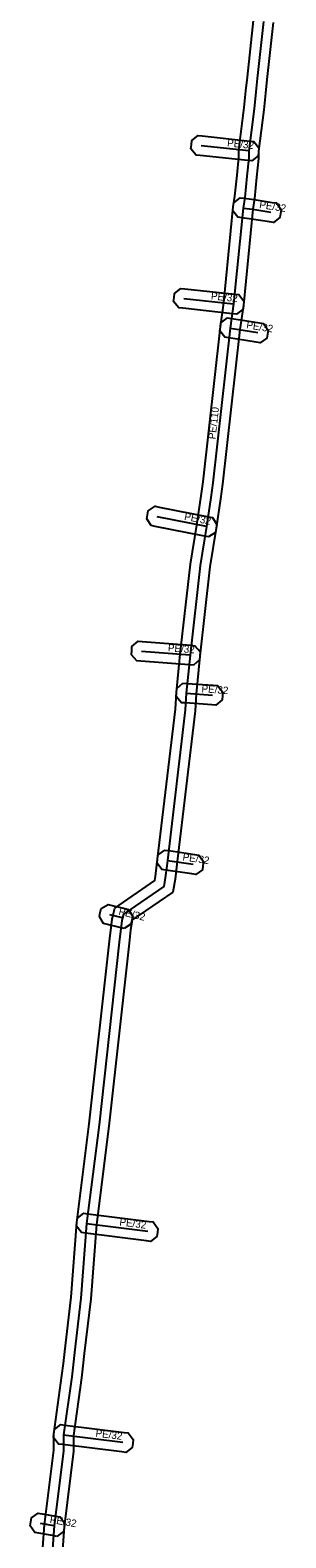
# Model space of a CAD drawing. Extents: x -772893 to -772575, y -1033735 to -1033288.
# Drawn here: x -772764.4 to -772738.4, y -1033585.9 to -1033432.5 of the extents above; entities that cross this region are included whole.
import ezdxf

# ---------------------------------------------------------------- set-up
doc = ezdxf.new("R2010")
doc.units = 0
for name, color, linetype in [('1', 7, 'Continuous'), ('24', 7, 'Continuous'), ('30', 7, 'Continuous')]:
    doc.layers.add(name, color=color, linetype=linetype)

msp = doc.modelspace()

# ---------------------------------------------------------------- linework, layer by layer
at = {"layer": '1'}
for points in [[(-772763.07, -1033586.93), (-772762.91, -1033584.62), (-772761.96, -1033577.01), (-772761.96, -1033575.38), (-772761.13, -1033569.41), (-772760.99, -1033568.21), (-772760.85, -1033566.96), (-772760.2, -1033561.44), (-772759.61, -1033553.84), (-772758.35, -1033543.8), (-772756.3, -1033525.22), (-772756.14, -1033523.82), (-772756.02, -1033523), (-772755.97, -1033522.67), (-772755.77, -1033521.86), (-772751.69, -1033519.06), (-772751.61, -1033518.63), (-772751.47, -1033517.44), (-772751.41, -1033516.89), (-772749.58, -1033501.62), (-772749.49, -1033499.91), (-772749.1, -1033496.02), (-772748.07, -1033486.85), (-772747.42, -1033482.88), (-772746.98, -1033479.92), (-772746.78, -1033478.48), (-772745.02, -1033462.72), (-772744.66, -1033460.27), (-772743.71, -1033450.5), (-772743.54, -1033449.42), (-772743.33, -1033447.28), (-772743.14, -1033445.47), (-772743.14, -1033444.74), (-772742.6, -1033440.4), (-772742.42, -1033438.71), (-772742.27, -1033437.33), (-772741.64, -1033431.55)], [(-772739.65, -1033431.75), (-772740.28, -1033437.55), (-772740.43, -1033438.93), (-772740.61, -1033440.63), (-772741.14, -1033444.86), (-772741.14, -1033445.58), (-772741.34, -1033447.48), (-772741.55, -1033449.67), (-772741.73, -1033450.76), (-772742.68, -1033460.51), (-772743.04, -1033462.98), (-772744.79, -1033478.73), (-772745, -1033480.21), (-772745.44, -1033483.19), (-772746.09, -1033487.12), (-772747.11, -1033496.22), (-772747.49, -1033500.07), (-772747.59, -1033501.79), (-772749.42, -1033517.12), (-772749.49, -1033517.68), (-772749.63, -1033518.93), (-772749.87, -1033520.24), (-772754.01, -1033523.07), (-772754.04, -1033523.29), (-772754.15, -1033524.08), (-772754.31, -1033525.44), (-772756.37, -1033544.03), (-772757.62, -1033554.04), (-772758.2, -1033561.63), (-772758.86, -1033567.19), (-772759, -1033568.44), (-772759.15, -1033569.66), (-772759.96, -1033575.52), (-772759.96, -1033577.13), (-772760.91, -1033584.82), (-772761.08, -1033587.14)]]:
    msp.add_lwpolyline(points, dxfattribs=at)
for points in [[(-772741.83, -1033445.84), (-772742.24, -1033445.79), (-772747.08, -1033445.28), (-772747.49, -1033445.24), (-772748.01, -1033444.6), (-772747.96, -1033444.19), (-772747.92, -1033443.77), (-772747.28, -1033443.25), (-772746.86, -1033443.3), (-772742.04, -1033443.81), (-772741.62, -1033443.85), (-772741.1, -1033444.49), (-772741.15, -1033444.91), (-772741.19, -1033445.32)], [(-772743, -1033449.59), (-772742.59, -1033449.64), (-772741.58, -1033449.77), (-772739.74, -1033450.05), (-772739.33, -1033450.11), (-772738.84, -1033450.78), (-772738.9, -1033451.19), (-772738.96, -1033451.6), (-772739.63, -1033452.09), (-772740.04, -1033452.03), (-772741.86, -1033451.75), (-772742.85, -1033451.62), (-772743.26, -1033451.57), (-772743.77, -1033450.91), (-772743.71, -1033450.5), (-772743.66, -1033450.09)], [(-772749.04, -1033458.8), (-772748.63, -1033458.85), (-772743.56, -1033459.4), (-772743.15, -1033459.44), (-772742.63, -1033460.09), (-772742.68, -1033460.5), (-772742.72, -1033460.91), (-772743.37, -1033461.43), (-772743.78, -1033461.38), (-772748.85, -1033460.83), (-772749.26, -1033460.79), (-772749.78, -1033460.14), (-772749.73, -1033459.73), (-772749.69, -1033459.32)], [(-772744.3, -1033461.8), (-772743.89, -1033461.86), (-772742.99, -1033461.99), (-772741.05, -1033462.3), (-772740.64, -1033462.37), (-772740.16, -1033463.04), (-772740.22, -1033463.45), (-772740.29, -1033463.86), (-772740.96, -1033464.34), (-772741.37, -1033464.28), (-772743.29, -1033463.97), (-772744.18, -1033463.84), (-772744.58, -1033463.78), (-772745.08, -1033463.11), (-772745.02, -1033462.71), (-772744.96, -1033462.3)], [(-772746.22, -1033484.09), (-772746.62, -1033484.01), (-772751.64, -1033483.02), (-772752.05, -1033482.94), (-772752.51, -1033482.25), (-772752.43, -1033481.85), (-772752.35, -1033481.44), (-772751.66, -1033480.98), (-772751.26, -1033481.06), (-772746.24, -1033482.05), (-772745.83, -1033482.13), (-772745.37, -1033482.82), (-772745.45, -1033483.22), (-772745.53, -1033483.63)], [(-772747.77, -1033497.15), (-772748.19, -1033497.12), (-772753.12, -1033496.74), (-772753.53, -1033496.71), (-772754.07, -1033496.08), (-772754.04, -1033495.66), (-772754.01, -1033495.25), (-772753.38, -1033494.71), (-772752.96, -1033494.74), (-772748.03, -1033495.12), (-772747.62, -1033495.16), (-772747.08, -1033495.78), (-772747.11, -1033496.2), (-772747.15, -1033496.61)], [(-772748.83, -1033498.96), (-772748.42, -1033498.99), (-772745.74, -1033499.19), (-772745.33, -1033499.22), (-772744.79, -1033499.85), (-772744.82, -1033500.27), (-772744.85, -1033500.68), (-772745.48, -1033501.22), (-772745.9, -1033501.19), (-772748.57, -1033500.99), (-772748.98, -1033500.96), (-772749.52, -1033500.33), (-772749.49, -1033499.92), (-772749.46, -1033499.5)], [(-772750.68, -1033515.95), (-772750.27, -1033516.01), (-772747.63, -1033516.4), (-772747.22, -1033516.46), (-772746.73, -1033517.12), (-772746.79, -1033517.54), (-772746.85, -1033517.95), (-772747.51, -1033518.44), (-772747.92, -1033518.38), (-772750.56, -1033517.99), (-772750.97, -1033517.93), (-772751.46, -1033517.27), (-772751.4, -1033516.86), (-772751.34, -1033516.45)], [(-772754.82, -1033523.93), (-772755.23, -1033523.83), (-772756.5, -1033523.52), (-772756.9, -1033523.42), (-772757.33, -1033522.71), (-772757.23, -1033522.31), (-772757.13, -1033521.91), (-772756.42, -1033521.48), (-772756.02, -1033521.58), (-772754.75, -1033521.89), (-772754.35, -1033521.99), (-772753.92, -1033522.7), (-772754.02, -1033523.1), (-772754.12, -1033523.5)], [(-772758.91, -1033552.9), (-772758.49, -1033552.95), (-772752.28, -1033553.74), (-772751.87, -1033553.79), (-772751.37, -1033554.45), (-772751.42, -1033554.86), (-772751.47, -1033555.27), (-772752.12, -1033555.77), (-772752.54, -1033555.72), (-772758.75, -1033554.93), (-772759.16, -1033554.88), (-772759.66, -1033554.22), (-772759.61, -1033553.81), (-772759.56, -1033553.4)], [(-772761.25, -1033574.41), (-772760.84, -1033574.46), (-772754.81, -1033575.21), (-772754.4, -1033575.26), (-772753.89, -1033575.91), (-772753.94, -1033576.32), (-772753.99, -1033576.73), (-772754.64, -1033577.24), (-772755.05, -1033577.19), (-772761.08, -1033576.44), (-772761.49, -1033576.39), (-772762, -1033575.74), (-772761.95, -1033575.33), (-772761.9, -1033574.92)], [(-772761.67, -1033585.78), (-772762.08, -1033585.71), (-772763.48, -1033585.47), (-772763.89, -1033585.4), (-772764.37, -1033584.72), (-772764.3, -1033584.31), (-772764.23, -1033583.9), (-772763.55, -1033583.42), (-772763.14, -1033583.49), (-772761.74, -1033583.73), (-772761.33, -1033583.8), (-772760.85, -1033584.48), (-772760.92, -1033584.89), (-772760.99, -1033585.3)]]:
    msp.add_lwpolyline(points, close=True, dxfattribs=at)
at = {"layer": '24'}
for points in [[(-772740.65, -1033431.65), (-772741.28, -1033437.44), (-772741.43, -1033438.82), (-772741.6, -1033440.52), (-772742.14, -1033444.8), (-772742.14, -1033445.53), (-772742.33, -1033447.38), (-772742.55, -1033449.55), (-772742.72, -1033450.63), (-772743.67, -1033460.39), (-772744.03, -1033462.85), (-772745.79, -1033478.6), (-772745.99, -1033480.07), (-772746.43, -1033483.03), (-772747.08, -1033486.99), (-772748.11, -1033496.12), (-772748.49, -1033499.99), (-772748.59, -1033501.7), (-772750.41, -1033517), (-772750.48, -1033517.56), (-772750.62, -1033518.78), (-772750.78, -1033519.65), (-772754.89, -1033522.47), (-772754.99, -1033522.86), (-772755.03, -1033523.15), (-772755.15, -1033523.95), (-772755.3, -1033525.33), (-772757.36, -1033543.92), (-772758.62, -1033553.94), (-772759.2, -1033561.54), (-772759.85, -1033567.08), (-772759.99, -1033568.33), (-772760.14, -1033569.54), (-772760.96, -1033575.45), (-772760.96, -1033577.07), (-772761.91, -1033584.72), (-772762.08, -1033587.04)], [(-772742.14, -1033444.8), (-772746.97, -1033444.29)], [(-772742.72, -1033450.63), (-772741.72, -1033450.76), (-772739.89, -1033451.04)], [(-772748.74, -1033459.84), (-772743.67, -1033460.39)], [(-772744.03, -1033462.85), (-772743.14, -1033462.98), (-772741.21, -1033463.29)], [(-772746.43, -1033483.03), (-772751.45, -1033482.04)], [(-772748.11, -1033496.12), (-772753.04, -1033495.74)], [(-772748.49, -1033499.99), (-772745.82, -1033500.19)], [(-772750.41, -1033517), (-772747.78, -1033517.39)], [(-772754.99, -1033522.86), (-772756.26, -1033522.55)], [(-772758.62, -1033553.94), (-772752.41, -1033554.73)], [(-772760.96, -1033575.45), (-772754.93, -1033576.2)], [(-772761.91, -1033584.72), (-772763.31, -1033584.48)]]:
    msp.add_lwpolyline(points, dxfattribs=at)

# ---------------------------------------------------------------- texts
at = {"layer": '30'}
for s, rotation, p in [('PE/32', 353.9725, (-772744.36, -1033444.35)), ('PE/32', 351.2656, (-772741.1, -1033450.62)), ('PE/32', 353.8087, (-772746.01, -1033459.92)), ('PE/32', 350.875, (-772742.42, -1033462.86)), ('PE/110', 83.6399, (-772745.52, -1033474.19)), ('PE/32', 348.8438, (-772748.74, -1033482.34)), ('PE/32', 355.5924, (-772750.38, -1033495.73)), ('PE/32', 355.7162, (-772746.96, -1033499.89)), ('PE/32', 351.6448, (-772748.9, -1033517)), ('PE/32', 346.2184, (-772755.42, -1033522.51)), ('PE/32', 352.7501, (-772755.32, -1033554.14)), ('PE/32', 352.9101, (-772757.75, -1033575.63)), ('PE/32', 350.2724, (-772762.41, -1033584.4))]:
    msp.add_text(s, height=0.75, rotation=rotation, dxfattribs=at).set_placement(p)

doc.saveas('drawing.dxf')
